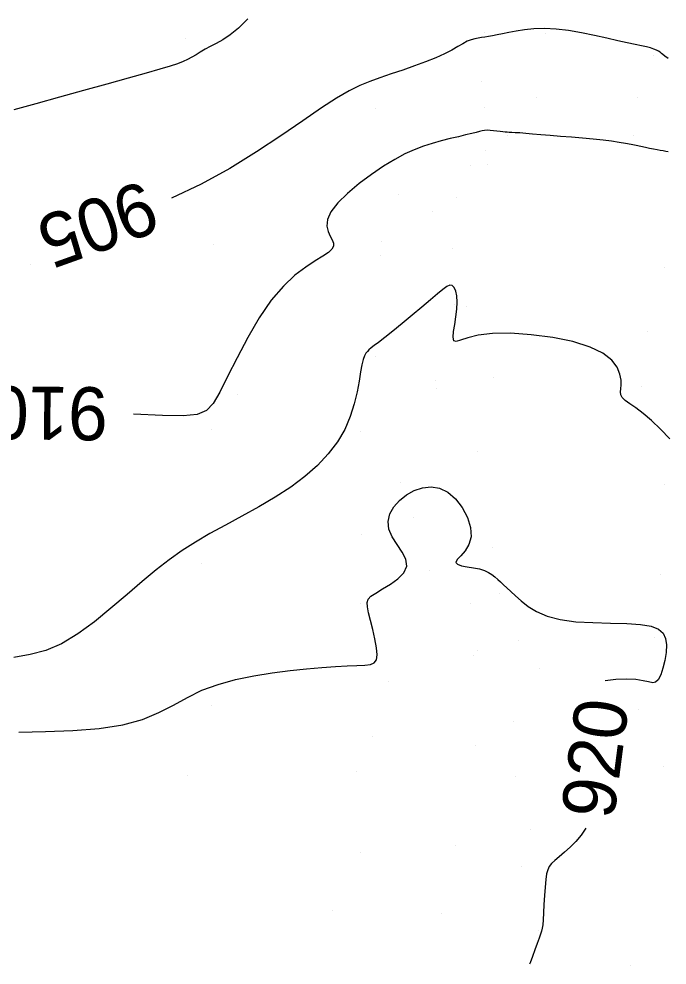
# Model space of a CAD drawing. Extents: x 400243 to 403697, y 4403637 to 4408083.
# Drawn here: x 402707.4 to 402798.8, y 4405856.6 to 4405990.2 of the extents above; entities that cross this region are included whole.
import ezdxf

# ---------------------------------------------------------------- set-up
doc = ezdxf.new("R2010")
doc.units = 0
doc.layers.add('HH_IC', color=7, linetype='Continuous')

msp = doc.modelspace()

# ---------------------------------------------------------------- linework, layer by layer
at = {"layer": 'HH_IC'}
for p, q in [((402772.98, 4405988.25), (402772.98, 4405988.25)), ((402781.63, 4405988.17), (402781.63, 4405988.17)), ((402730.85, 4405987.45), (402730.85, 4405987.45)), ((402796.89, 4405985.05), (402796.89, 4405985.05)), ((402772.64, 4405981.38), (402772.64, 4405981.38)), ((402780.39, 4405979.12), (402780.39, 4405979.12)), ((402794.6, 4405979.09), (402794.6, 4405979.09)), ((402757.66, 4405977.54), (402757.66, 4405977.54)), ((402772.99, 4405977.71), (402772.99, 4405977.71)), ((402776.33, 4405973.81), (402776.33, 4405973.81)), ((402794, 4405973.76), (402794, 4405973.76)), ((402773.12, 4405971.59), (402773.12, 4405971.59)), ((402771.13, 4405969.51), (402771.13, 4405969.51)), ((402773.45, 4405969.65), (402773.45, 4405969.65)), ((402760.85, 4405965.38), (402760.85, 4405965.38)), ((402769.15, 4405965.04), (402769.15, 4405965.04)), ((402765.66, 4405963.07), (402765.66, 4405963.07)), ((402758.48, 4405958.77), (402758.48, 4405958.77)), ((402734.87, 4405958.34), (402734.87, 4405958.34)), ((402768.56, 4405957.76), (402768.56, 4405957.76)), ((402758.39, 4405956.74), (402758.39, 4405956.74)), ((402708.98, 4405955.5), (402708.98, 4405955.5)), ((402798.38, 4405955.12), (402798.38, 4405955.12)), ((402768.85, 4405949.88), (402768.85, 4405949.88)), ((402770.57, 4405949.57), (402770.57, 4405949.57)), ((402796.04, 4405946.1), (402796.04, 4405946.1)), ((402757.65, 4405942.61), (402757.65, 4405942.61)), ((402766.12, 4405939.13), (402766.12, 4405939.13)), ((402774.26, 4405939.53), (402774.26, 4405939.53)), ((402795.2, 4405938.36), (402795.2, 4405938.36)), ((402738.22, 4405937.15), (402738.22, 4405937.15)), ((402766.21, 4405938.03), (402766.21, 4405938.03)), ((402734.54, 4405932.24), (402734.54, 4405932.24)), ((402755.6, 4405931.98), (402755.6, 4405931.98)), ((402772.04, 4405929.08), (402772.04, 4405929.08)), ((402761.13, 4405924.83), (402761.13, 4405924.83)), ((402798.43, 4405924.48), (402798.43, 4405924.48)), ((402762.97, 4405919.88), (402762.97, 4405919.88)), ((402755.73, 4405917.47), (402755.73, 4405917.47)), ((402774.11, 4405915.64), (402774.11, 4405915.64)), ((402733.08, 4405913.28), (402733.08, 4405913.28)), ((402765.24, 4405912.36), (402765.24, 4405912.36)), ((402797.92, 4405911.83), (402797.92, 4405911.83)), ((402775.21, 4405909.04), (402775.21, 4405909.04)), ((402755.52, 4405907.72), (402755.52, 4405907.72)), ((402756.38, 4405907.63), (402756.38, 4405907.63)), ((402771.01, 4405907.62), (402771.01, 4405907.62)), ((402777.87, 4405902.52), (402777.87, 4405902.52)), ((402797, 4405902.87), (402797, 4405902.87)), ((402772.04, 4405901.11), (402772.04, 4405901.11)), ((402771.42, 4405900.36), (402771.42, 4405900.36)), ((402780.82, 4405898.53), (402780.82, 4405898.53)), ((402759.53, 4405896.62), (402759.53, 4405896.62)), ((402734.48, 4405893.34), (402734.48, 4405893.34)), ((402794.79, 4405892.75), (402794.79, 4405892.75)), ((402777.09, 4405891.01), (402777.09, 4405891.01)), ((402757.26, 4405888.86), (402757.26, 4405888.86)), ((402771.7, 4405887.67), (402771.7, 4405887.67)), ((402755.03, 4405883.99), (402755.03, 4405883.99)), ((402798.28, 4405884.69), (402798.28, 4405884.69)), ((402731.21, 4405883.45), (402731.21, 4405883.45)), ((402777.38, 4405883.32), (402777.38, 4405883.32)), ((402779.47, 4405875.76), (402779.47, 4405875.76)), ((402768.99, 4405873.48), (402768.99, 4405873.48)), ((402755.56, 4405872.53), (402755.56, 4405872.53)), ((402778.3, 4405870.6), (402778.3, 4405870.6)), ((402751.61, 4405864.39), (402751.61, 4405864.39)), ((402766.97, 4405863.95), (402766.97, 4405863.95)), ((402780.64, 4405861.59), (402780.64, 4405861.59)), ((402793.63, 4405856.64), (402793.63, 4405856.64))]:
    msp.add_line(p, q, dxfattribs=at)
for points in [[(402739.66, 4405990.2), (402738.35, 4405988.91), (402737.18, 4405987.96), (402736.13, 4405987.27), (402735.19, 4405986.75), (402734.36, 4405986.33), (402733.62, 4405985.92), (402732.96, 4405985.52), (402732.35, 4405985.15), (402731.76, 4405984.79), (402731.17, 4405984.47), (402730.54, 4405984.17), (402729.76, 4405983.87), (402728.71, 4405983.53), (402727.27, 4405983.1), (402725.32, 4405982.54), (402722.78, 4405981.82), (402719.79, 4405980.99), (402716.5, 4405980.08), (402713.1, 4405979.14), (402709.77, 4405978.22), (402706.64, 4405977.36)], [(402798.95, 4405984.62), (402798.48, 4405984.94), (402798.19, 4405985.17), (402798, 4405985.34), (402797.8, 4405985.49), (402797.57, 4405985.65), (402797.28, 4405985.8), (402796.92, 4405985.95), (402796.46, 4405986.1), (402795.89, 4405986.25), (402795.16, 4405986.4), (402794.27, 4405986.59), (402793.17, 4405986.82), (402791.85, 4405987.11), (402790.29, 4405987.47), (402788.55, 4405987.86), (402786.73, 4405988.23), (402784.89, 4405988.55), (402783.13, 4405988.76), (402781.5, 4405988.83), (402780.02, 4405988.79), (402778.69, 4405988.66), (402777.52, 4405988.49), (402776.49, 4405988.3), (402775.6, 4405988.12), (402774.84, 4405987.96), (402774.19, 4405987.83), (402773.61, 4405987.72), (402773.09, 4405987.63), (402772.61, 4405987.57), (402772.14, 4405987.5), (402771.67, 4405987.41), (402771.16, 4405987.27), (402770.61, 4405987.04), (402769.99, 4405986.71), (402769.27, 4405986.29), (402768.41, 4405985.81), (402767.39, 4405985.27), (402766.17, 4405984.7), (402764.74, 4405984.13), (402763.16, 4405983.56), (402761.5, 4405982.99), (402759.86, 4405982.44), (402758.3, 4405981.91), (402756.86, 4405981.39), (402755.46, 4405980.8), (402753.94, 4405980.04), (402752.18, 4405979.02), (402750.04, 4405977.64), (402747.41, 4405975.84), (402744.33, 4405973.72), (402740.88, 4405971.43), (402737.1, 4405969.1), (402733.08, 4405966.88), (402728.9, 4405964.89)], [(402798.95, 4405971.45), (402798.62, 4405971.51), (402798.25, 4405971.57), (402797.83, 4405971.64), (402797.37, 4405971.72), (402796.87, 4405971.82), (402796.33, 4405971.93), (402795.74, 4405972.06), (402795.11, 4405972.2), (402794.44, 4405972.34), (402793.72, 4405972.49), (402792.92, 4405972.63), (402792.01, 4405972.78), (402790.97, 4405972.93), (402789.77, 4405973.07), (402788.38, 4405973.22), (402786.87, 4405973.36), (402785.31, 4405973.49), (402783.76, 4405973.62), (402782.3, 4405973.75), (402780.98, 4405973.85), (402779.83, 4405973.95), (402778.85, 4405974.03), (402778.03, 4405974.1), (402777.38, 4405974.14), (402776.9, 4405974.17), (402776.54, 4405974.19), (402776.24, 4405974.2), (402775.96, 4405974.22), (402775.64, 4405974.25), (402775.24, 4405974.3), (402774.78, 4405974.36), (402774.3, 4405974.42), (402773.83, 4405974.47), (402773.41, 4405974.49), (402773.05, 4405974.47), (402772.72, 4405974.41), (402772.35, 4405974.32), (402771.87, 4405974.19), (402771.23, 4405974.02), (402770.38, 4405973.82), (402769.35, 4405973.58), (402768.19, 4405973.3), (402766.95, 4405972.99), (402765.68, 4405972.63), (402764.42, 4405972.23), (402763.14, 4405971.74), (402761.81, 4405971.14), (402760.38, 4405970.38), (402758.81, 4405969.42), (402757.1, 4405968.26), (402755.36, 4405966.95), (402753.73, 4405965.58), (402752.35, 4405964.23), (402751.37, 4405962.98), (402750.88, 4405961.89), (402750.79, 4405960.97), (402750.97, 4405960.2), (402751.28, 4405959.55), (402751.57, 4405959), (402751.74, 4405958.54), (402751.73, 4405958.12), (402751.5, 4405957.7), (402751.02, 4405957.24), (402750.25, 4405956.71), (402749.17, 4405956.05), (402747.83, 4405955.18), (402746.31, 4405954.03), (402744.67, 4405952.49), (402742.97, 4405950.5), (402741.28, 4405948.01), (402739.66, 4405945.21), (402738.15, 4405942.37), (402736.81, 4405939.71), (402735.69, 4405937.5), (402734.77, 4405935.92), (402733.81, 4405934.92), (402732.51, 4405934.38), (402730.54, 4405934.18), (402727.62, 4405934.22), (402723.55, 4405934.4)], [(402799.19, 4405930.92), (402797.86, 4405932.3), (402796.58, 4405933.53), (402795.42, 4405934.52), (402794.4, 4405935.29), (402793.56, 4405935.89), (402792.9, 4405936.36), (402792.47, 4405936.77), (402792.26, 4405937.15), (402792.21, 4405937.54), (402792.26, 4405937.99), (402792.31, 4405938.54), (402792.3, 4405939.22), (402792.15, 4405940.07), (402791.74, 4405941.02), (402790.98, 4405942.02), (402789.75, 4405943), (402787.94, 4405943.89), (402785.51, 4405944.65), (402782.66, 4405945.23), (402779.64, 4405945.63), (402776.72, 4405945.82), (402774.15, 4405945.79), (402772.15, 4405945.54), (402770.68, 4405945.19), (402769.67, 4405944.85), (402769.04, 4405944.67), (402768.72, 4405944.77), (402768.62, 4405945.26), (402768.69, 4405946.06), (402768.84, 4405947.06), (402769.02, 4405948.16), (402769.16, 4405949.25), (402769.2, 4405950.24), (402769.14, 4405951.09), (402769, 4405951.77), (402768.78, 4405952.27), (402768.5, 4405952.55), (402768.16, 4405952.6), (402767.72, 4405952.41), (402767.15, 4405952.01), (402766.4, 4405951.38), (402765.42, 4405950.55), (402764.21, 4405949.52), (402762.85, 4405948.37), (402761.45, 4405947.21), (402760.12, 4405946.13), (402758.98, 4405945.22), (402758.11, 4405944.54), (402757.49, 4405944.08), (402757.05, 4405943.75), (402756.74, 4405943.5), (402756.52, 4405943.27), (402756.31, 4405943), (402756.13, 4405942.63), (402755.94, 4405942.11), (402755.76, 4405941.37), (402755.56, 4405940.38), (402755.35, 4405939.09), (402755.06, 4405937.55), (402754.66, 4405935.85), (402754.1, 4405934.06), (402753.32, 4405932.25), (402752.29, 4405930.49), (402751, 4405928.8), (402749.47, 4405927.17), (402747.7, 4405925.61), (402745.71, 4405924.11), (402743.51, 4405922.69), (402741.19, 4405921.32), (402738.82, 4405920.02), (402736.49, 4405918.76), (402734.29, 4405917.54), (402732.28, 4405916.35), (402730.4, 4405915.15), (402728.57, 4405913.86), (402726.72, 4405912.43), (402724.75, 4405910.81), (402722.62, 4405908.97), (402720.35, 4405907.02), (402718.02, 4405905.11), (402715.67, 4405903.39), (402713.37, 4405902.01), (402711.16, 4405901.06), (402708.96, 4405900.46), (402706.68, 4405900.06)], [(402707.36, 4405889.51), (402711.11, 4405889.6), (402714.98, 4405889.76), (402718.71, 4405890.05), (402722.04, 4405890.55), (402724.82, 4405891.32), (402727.13, 4405892.28), (402729.17, 4405893.35), (402731.13, 4405894.43), (402733.18, 4405895.43), (402735.47, 4405896.27), (402737.94, 4405896.94), (402740.52, 4405897.48), (402743.11, 4405897.9), (402745.61, 4405898.23), (402747.95, 4405898.47), (402750.09, 4405898.65), (402752.01, 4405898.78), (402753.67, 4405898.86), (402755.05, 4405898.92), (402756.14, 4405898.96), (402756.95, 4405899.06), (402757.49, 4405899.29), (402757.8, 4405899.72), (402757.9, 4405900.42), (402757.81, 4405901.44), (402757.59, 4405902.67), (402757.29, 4405903.99), (402756.97, 4405905.27), (402756.7, 4405906.37), (402756.52, 4405907.2), (402756.48, 4405907.8), (402756.63, 4405908.28), (402757.02, 4405908.7), (402757.69, 4405909.16), (402758.65, 4405909.73), (402759.76, 4405910.4), (402760.82, 4405911.17), (402761.66, 4405912.02), (402762.08, 4405912.94), (402761.96, 4405913.92), (402761.44, 4405914.94), (402760.73, 4405916), (402760.03, 4405917.08), (402759.55, 4405918.17), (402759.44, 4405919.26), (402759.7, 4405920.33), (402760.26, 4405921.33), (402761.06, 4405922.24), (402762.03, 4405923.02), (402763.12, 4405923.63), (402764.29, 4405924.03), (402765.5, 4405924.17), (402766.71, 4405923.98), (402767.88, 4405923.42), (402768.96, 4405922.47), (402769.9, 4405921.23), (402770.63, 4405919.83), (402771.06, 4405918.41), (402771.15, 4405917.09), (402770.84, 4405915.99), (402770.29, 4405915.11), (402769.68, 4405914.41), (402769.18, 4405913.88), (402768.98, 4405913.49), (402769.21, 4405913.22), (402769.79, 4405913.02), (402770.58, 4405912.87), (402771.47, 4405912.73), (402772.32, 4405912.57), (402773.03, 4405912.35), (402773.61, 4405912.08), (402774.09, 4405911.78), (402774.51, 4405911.44), (402774.9, 4405911.09), (402775.3, 4405910.73), (402775.73, 4405910.33), (402776.21, 4405909.89), (402776.77, 4405909.37), (402777.43, 4405908.76), (402778.22, 4405908.04), (402779.18, 4405907.28), (402780.38, 4405906.54), (402781.87, 4405905.89), (402783.71, 4405905.4), (402785.91, 4405905.11), (402788.33, 4405904.98), (402790.79, 4405904.92), (402793.1, 4405904.87), (402795.06, 4405904.74), (402796.54, 4405904.48), (402797.57, 4405904.06), (402798.22, 4405903.49), (402798.57, 4405902.75), (402798.69, 4405901.84), (402798.64, 4405900.76), (402798.47, 4405899.63), (402798.21, 4405898.53), (402797.89, 4405897.59), (402797.54, 4405896.9), (402797.18, 4405896.56), (402796.76, 4405896.49), (402796.19, 4405896.6), (402795.43, 4405896.78), (402794.39, 4405896.95), (402793.06, 4405897.01), (402791.55, 4405896.95), (402790.04, 4405896.75)], [(402787.34, 4405875.98), (402786.67, 4405874.99), (402785.91, 4405874.08), (402785.11, 4405873.28), (402784.31, 4405872.56), (402783.58, 4405871.94), (402782.96, 4405871.42), (402782.5, 4405870.98), (402782.17, 4405870.57), (402781.95, 4405870.1), (402781.8, 4405869.51), (402781.69, 4405868.71), (402781.6, 4405867.66), (402781.51, 4405866.45), (402781.43, 4405865.2), (402781.37, 4405864.02), (402781.31, 4405863.04), (402781.25, 4405862.33), (402781.19, 4405861.83), (402781.1, 4405861.42), (402780.96, 4405860.99), (402780.76, 4405860.43), (402780.48, 4405859.68), (402780.15, 4405858.79), (402779.81, 4405857.85), (402779.48, 4405856.96), (402779.41, 4405856.79)]]:
    msp.add_lwpolyline(points, dxfattribs=at)

# ---------------------------------------------------------------- texts
for s, rotation, p in [('905', 199.7131, (402725.13, 4405967.52)), ('910', 179.355, (402719.96, 4405938.19)), ('920', 82.5836, (402791.26, 4405877.05))]:
    msp.add_text(s, height=7.5, rotation=rotation, dxfattribs=at).set_placement(p)

doc.saveas('drawing.dxf')
